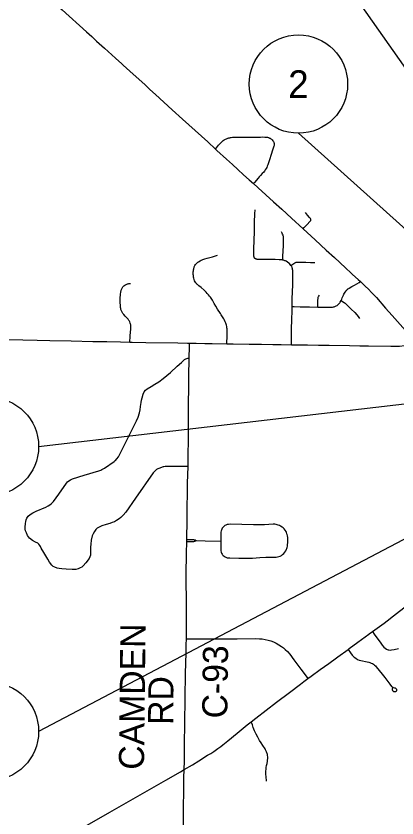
# Model space of a CAD drawing. Extents: x 1341221 to 1914484, y 79347 to 658398.
# Drawn here: x 1374791 to 1383630, y 603681 to 622283 of the extents above; entities that cross this region are included whole.
import ezdxf

# ---------------------------------------------------------------- set-up
doc = ezdxf.new("R2010")
doc.units = 0
for name, color, linetype in [('GM_X_County', 7, 'Continuous'), ('GM_X_County_Road_Text', 7, 'Continuous'), ('GM_X_Major_Lake_Text', 7, 'Continuous'), ('GM_X_State_Location', 7, 'Continuous'), ('GM_X_State_Shield', 7, 'Continuous'), ('GM_X_Township_Text', 7, 'Continuous'), ('GM_X_Unincorporated', 7, 'Continuous'), ('GM_X_US_Shield', 7, 'Continuous')]:
    doc.layers.add(name, color=color, linetype=linetype)

msp = doc.modelspace()

# ---------------------------------------------------------------- linework, layer by layer
at = {"layer": 'GM_X_County'}
for p, q in [((1382167, 623424), (1387231, 616228)), ((1381344, 619564), (1386235, 615180))]:
    msp.add_line(p, q, dxfattribs=at)
for centre in [(1381344, 620705), (1374174, 612298), (1374174, 605688)]:
    msp.add_circle(centre, 1141, dxfattribs=at)
at = {"layer": 'GM_X_County_Road_Text'}
for p, q in [((1375315, 612298), (1387479, 613715)), ((1387479, 612081), (1375315, 605688))]:
    msp.add_line(p, q, dxfattribs=at)
at = {"layer": 'GM_X_State_Location'}
msp.add_line((1378605, 604754), (1378695, 604806), dxfattribs=at)
for points in [[(1374346, 614781), (1374947, 614768), (1375280, 614764), (1375574, 614758), (1376073, 614747), (1376572, 614736), (1376898, 614730), (1377218, 614722), (1377435, 614716), (1377486, 614715), (1377806, 614710), (1378547, 614699), (1378771, 614697), (1378817, 614696), (1378969, 614693), (1379168, 614688), (1379341, 614687), (1379684, 614682), (1379833, 614679), (1380204, 614674), (1380485, 614670), (1380752, 614663), (1380944, 614662), (1381180, 614659), (1381289, 614658), (1381430, 614657), (1381551, 614654)], [(1381551, 614654), (1381813, 614650), (1382055, 614646), (1382528, 614638), (1382771, 614634), (1382968, 614630), (1383488, 614621), (1383577, 614621), (1383686, 614627), (1383808, 614638), (1383833, 614641), (1383998, 614665), (1384099, 614683), (1384167, 614697)], [(1383473, 608310), (1383481, 608316), (1383691, 608481), (1383818, 608577), (1383892, 608636), (1383985, 608720), (1384113, 608833), (1384175, 608887), (1384262, 608963)], [(1382977, 607942), (1382985, 607948), (1383059, 608003), (1383332, 608203), (1383473, 608310)], [(1382224, 607394), (1382257, 607418), (1382495, 607591), (1382520, 607609), (1382719, 607757), (1382977, 607942)], [(1381472, 606847), (1381563, 606916), (1381639, 606973), (1381851, 607127), (1382050, 607267), (1382224, 607394)], [(1378695, 604806), (1378883, 604916), (1379030, 605006), (1379237, 605134), (1379308, 605178), (1379377, 605225), (1379477, 605294), (1379542, 605340), (1379590, 605379), (1379705, 605471), (1379923, 605648), (1380156, 605838), (1380248, 605912), (1380356, 605998), (1380836, 606370), (1381133, 606593), (1381390, 606784), (1381472, 606847)], [(1369197, 599284), (1369239, 599316), (1369336, 599389), (1369617, 599601), (1369739, 599687), (1369792, 599722), (1369899, 599790), (1370152, 599941), (1371027, 600446), (1371722, 600842), (1372205, 601120), (1372852, 601483), (1373372, 601772), (1375078, 602744), (1375736, 603114), (1375804, 603153), (1376176, 603363), (1376498, 603548), (1376965, 603813), (1377238, 603969), (1378266, 604560), (1378605, 604754)]]:
    msp.add_lwpolyline(points, dxfattribs=at)
at = {"layer": 'GM_X_State_Shield'}
for points in [[(1379419, 619197), (1379444, 619226), (1379492, 619284), (1379551, 619346), (1379568, 619364), (1379582, 619378), (1379600, 619393), (1379624, 619410), (1379637, 619417), (1379649, 619424), (1379674, 619435), (1379689, 619442), (1379704, 619448), (1379716, 619452), (1379729, 619456), (1379749, 619460), (1379770, 619465), (1379786, 619467), (1379814, 619470), (1379847, 619471), (1379875, 619472), (1379924, 619472), (1379975, 619471), (1380066, 619472), (1380172, 619473), (1380310, 619475), (1380409, 619476), (1380463, 619476), (1380521, 619477), (1380567, 619476), (1380598, 619474), (1380612, 619472), (1380624, 619470), (1380639, 619466), (1380651, 619462), (1380662, 619458), (1380674, 619453), (1380685, 619447), (1380695, 619441), (1380706, 619434), (1380717, 619426), (1380725, 619418), (1380735, 619408), (1380751, 619388), (1380757, 619379), (1380762, 619371), (1380769, 619358), (1380774, 619344), (1380778, 619332), (1380779, 619322), (1380780, 619311), (1380780, 619301), (1380779, 619290), (1380777, 619278), (1380772, 619262), (1380767, 619244), (1380752, 619198), (1380736, 619148), (1380718, 619093), (1380702, 619045), (1380678, 618973), (1380654, 618898), (1380632, 618831), (1380621, 618800), (1380609, 618772), (1380596, 618748), (1380574, 618713), (1380556, 618687), (1380537, 618663), (1380505, 618627), (1380465, 618582), (1380436, 618551), (1380406, 618520), (1380323, 618424), (1380298, 618395)], [(1381180, 614659), (1381180, 614725), (1381182, 614868), (1381185, 615034), (1381186, 615089), (1381189, 615175), (1381198, 615516), (1381199, 615543), (1381202, 615721), (1381210, 616047), (1381215, 616283), (1381215, 616318), (1381213, 616352), (1381212, 616378), (1381208, 616403), (1381205, 616421), (1381200, 616439), (1381195, 616454), (1381189, 616468), (1381181, 616482), (1381171, 616497), (1381150, 616522), (1381134, 616539), (1381119, 616553), (1381089, 616576), (1381057, 616595), (1381043, 616602), (1381029, 616608), (1381000, 616617), (1380978, 616622), (1380964, 616625), (1380944, 616627), (1380921, 616630), (1380894, 616631), (1380805, 616634), (1380562, 616638), (1380415, 616638), (1380395, 616638), (1380384, 616639), (1380375, 616641), (1380365, 616643), (1380354, 616647), (1380345, 616651), (1380336, 616656), (1380330, 616662), (1380325, 616667), (1380321, 616673), (1380318, 616680), (1380315, 616687), (1380313, 616694), (1380311, 616704), (1380310, 616721), (1380312, 616903), (1380315, 617049), (1380322, 617305), (1380328, 617502), (1380334, 617694), (1380337, 617787)], [(1381450, 617347), (1381479, 617378), (1381543, 617447), (1381612, 617519), (1381626, 617533), (1381631, 617540), (1381634, 617545), (1381635, 617552), (1381635, 617558), (1381634, 617564), (1381632, 617569), (1381630, 617575), (1381627, 617579), (1381624, 617584), (1381604, 617607), (1381553, 617666), (1381506, 617725)], [(1380978, 616622), (1380985, 616705), (1380995, 616961), (1380997, 617064), (1380997, 617118), (1380996, 617146), (1380994, 617165), (1380991, 617185), (1380986, 617203), (1380977, 617224), (1380967, 617243), (1380951, 617274)], [(1379684, 614682), (1379685, 614715), (1379689, 614830), (1379691, 614929), (1379691, 614963), (1379690, 614995), (1379689, 615024), (1379685, 615053), (1379680, 615081), (1379674, 615110), (1379666, 615138), (1379658, 615161), (1379647, 615190), (1379630, 615226), (1379612, 615258), (1379598, 615283), (1379583, 615308), (1379554, 615350), (1379533, 615381), (1379464, 615485), (1379424, 615554), (1379388, 615618), (1379347, 615690), (1379304, 615759), (1379282, 615788), (1379257, 615818), (1379228, 615849), (1379204, 615875), (1379155, 615924), (1379087, 615982), (1379034, 616025), (1379005, 616052), (1378989, 616066), (1378977, 616080), (1378962, 616097), (1378948, 616119), (1378935, 616144), (1378923, 616175), (1378913, 616205), (1378909, 616225), (1378907, 616243), (1378905, 616264), (1378904, 616288), (1378904, 616346), (1378906, 616372), (1378909, 616397), (1378913, 616416), (1378916, 616434), (1378921, 616449), (1378927, 616464), (1378934, 616479), (1378941, 616493), (1378959, 616520), (1378975, 616539), (1378993, 616557), (1379008, 616570), (1379023, 616581), (1379061, 616605), (1379089, 616621), (1379106, 616628), (1379128, 616637), (1379168, 616650), (1379225, 616666), (1379346, 616698), (1379464, 616733)], [(1381171, 616497), (1381213, 616525), (1381260, 616556), (1381273, 616564), (1381289, 616570), (1381301, 616572), (1381314, 616574), (1381344, 616575), (1381398, 616574), (1381519, 616570), (1381624, 616568), (1381725, 616566)], [(1381199, 615543), (1381247, 615542), (1381384, 615540), (1381463, 615539), (1381604, 615536), (1381791, 615532), (1381852, 615531), (1381954, 615529), (1382063, 615528), (1382093, 615528), (1382118, 615529), (1382138, 615531), (1382154, 615534), (1382170, 615537), (1382187, 615543), (1382204, 615550), (1382223, 615560), (1382242, 615571), (1382256, 615581), (1382269, 615592), (1382283, 615605), (1382296, 615620), (1382305, 615631), (1382315, 615645), (1382336, 615685), (1382349, 615714), (1382361, 615743), (1382374, 615775), (1382386, 615804), (1382398, 615829), (1382412, 615855), (1382426, 615877), (1382448, 615908), (1382457, 615919), (1382467, 615931), (1382479, 615942), (1382493, 615954), (1382510, 615966), (1382521, 615974), (1382579, 616006), (1382647, 616043), (1382752, 616103), (1382783, 616121)], [(1377435, 614716), (1377435, 614740), (1377436, 614830), (1377438, 614867), (1377452, 615025), (1377454, 615054), (1377455, 615077), (1377454, 615098), (1377451, 615119), (1377446, 615138), (1377440, 615162), (1377432, 615187), (1377422, 615207), (1377411, 615224), (1377402, 615234), (1377389, 615251), (1377375, 615265), (1377324, 615321), (1377292, 615357), (1377271, 615384), (1377253, 615412), (1377239, 615442), (1377232, 615458), (1377226, 615477), (1377221, 615499), (1377218, 615523), (1377214, 615564), (1377209, 615648), (1377208, 615693), (1377210, 615748), (1377214, 615817), (1377215, 615842), (1377219, 615870), (1377223, 615890), (1377227, 615907), (1377233, 615925), (1377240, 615943), (1377254, 615972), (1377263, 615985), (1377272, 615998), (1377294, 616021), (1377319, 616041), (1377331, 616049), (1377347, 616057), (1377377, 616069), (1377395, 616073), (1377408, 616076), (1377446, 616080)], [(1381791, 615532), (1381792, 615568), (1381794, 615633), (1381797, 615688), (1381800, 615731), (1381801, 615744), (1381805, 615759), (1381811, 615774), (1381818, 615788), (1381831, 615809)], [(1382336, 615685), (1382360, 615668), (1382410, 615633), (1382428, 615620), (1382447, 615604), (1382476, 615576), (1382571, 615483), (1382650, 615404), (1382696, 615354), (1382727, 615315), (1382761, 615270)], [(1378969, 610117), (1379182, 610109), (1379540, 610104), (1379540, 610002), (1379541, 609914), (1379544, 609878), (1379551, 609847), (1379559, 609822), (1379571, 609801), (1379584, 609784), (1379599, 609767), (1379620, 609750), (1379644, 609736), (1379671, 609723), (1379693, 609718), (1379717, 609714), (1379752, 609712), (1379962, 609707), (1380160, 609706), (1380275, 609710), (1380447, 609722), (1380587, 609728), (1380708, 609727), (1380795, 609728), (1380826, 609730), (1380857, 609735), (1380886, 609743), (1380917, 609754), (1380947, 609771), (1380977, 609790), (1381003, 609816), (1381027, 609845), (1381049, 609876), (1381067, 609912), (1381075, 609931), (1381082, 609952), (1381088, 609987), (1381093, 610021), (1381097, 610062), (1381099, 610095), (1381098, 610138), (1381094, 610190), (1381089, 610226), (1381083, 610254), (1381078, 610272), (1381068, 610300), (1381056, 610323), (1381037, 610355), (1381014, 610384), (1380989, 610408), (1380963, 610429), (1380929, 610449), (1380901, 610463), (1380875, 610475), (1380853, 610482), (1380827, 610488), (1380794, 610492), (1380757, 610492), (1380559, 610482), (1380303, 610480), (1379759, 610493), (1379722, 610490), (1379693, 610486), (1379673, 610480), (1379657, 610472), (1379639, 610461), (1379622, 610450), (1379605, 610437), (1379591, 610421), (1379576, 610401), (1379564, 610379), (1379556, 610358), (1379550, 610338), (1379546, 610311), (1379541, 610192), (1379540, 610104)], [(1378752, 610143), (1378892, 610138), (1378909, 610137), (1378923, 610135), (1378934, 610133), (1378946, 610130), (1378959, 610125), (1378969, 610117)], [(1378752, 610093), (1378804, 610094), (1378893, 610095), (1378915, 610096), (1378930, 610098), (1378944, 610103), (1378955, 610109), (1378969, 610117)], [(1383059, 608003), (1383100, 607945), (1383160, 607862), (1383237, 607760), (1383290, 607689), (1383327, 607646), (1383354, 607621), (1383385, 607599), (1383406, 607588), (1383424, 607581), (1383441, 607577), (1383470, 607574), (1383507, 607577), (1383563, 607588), (1383663, 607608)], [(1378743, 607839), (1378951, 607837), (1379188, 607836), (1379514, 607835), (1379706, 607836), (1379924, 607837), (1380353, 607841), (1380442, 607839), (1380505, 607833), (1380568, 607823), (1380642, 607806), (1380703, 607788), (1380762, 607765), (1380825, 607735), (1380891, 607699), (1380950, 607661), (1380996, 607627), (1381038, 607589), (1381087, 607540), (1381141, 607477), (1381240, 607351), (1381400, 607136), (1381499, 607002), (1381563, 606916)], [(1382495, 607591), (1382554, 607512), (1382593, 607459), (1382615, 607432), (1382638, 607411), (1382673, 607385), (1382716, 607360), (1382756, 607342), (1382792, 607331), (1382942, 607302), (1382979, 607292), (1382998, 607286), (1383030, 607274), (1383059, 607261), (1383083, 607246), (1383109, 607228), (1383130, 607207), (1383147, 607189), (1383283, 607018), (1383345, 606937), (1383468, 606782), (1383507, 606731), (1383517, 606722), (1383526, 606715), (1383534, 606711), (1383541, 606708), (1383573, 606700), (1383585, 606696), (1383593, 606692), (1383605, 606683), (1383612, 606674), (1383618, 606666), (1383622, 606658), (1383623, 606650), (1383623, 606641), (1383621, 606633), (1383618, 606626), (1383613, 606619), (1383607, 606613), (1383601, 606608), (1383593, 606605), (1383585, 606603), (1383577, 606603), (1383569, 606604), (1383561, 606606), (1383554, 606610), (1383548, 606614), (1383541, 606621), (1383536, 606628), (1383533, 606635), (1383529, 606644), (1383528, 606654), (1383527, 606663), (1383529, 606676), (1383533, 606706)]]:
    msp.add_lwpolyline(points, dxfattribs=at)
at = {"layer": 'GM_X_Township_Text'}
for points in [[(1378678, 603955), (1378685, 604282), (1378685, 604492), (1378686, 604657), (1378688, 604691), (1378689, 604730), (1378695, 604806)], [(1378657, 598745), (1378656, 598778), (1378658, 599145), (1378659, 600047), (1378658, 600341), (1378663, 600917), (1378665, 601153), (1378667, 601518), (1378671, 601934), (1378671, 602151), (1378674, 602407), (1378673, 602605), (1378673, 602784), (1378674, 603085), (1378675, 603411), (1378677, 603782), (1378678, 603955)]]:
    msp.add_lwpolyline(points, dxfattribs=at)
at = {"layer": 'GM_X_Unincorporated'}
msp.add_line((1376608, 621750), (1376661, 621703), dxfattribs=at)
for points in [[(1375272, 622961), (1375606, 622657), (1375860, 622427), (1376428, 621913), (1376547, 621807), (1376608, 621750)], [(1376661, 621703), (1376842, 621540), (1377099, 621306), (1377244, 621174), (1377279, 621140)], [(1377279, 621140), (1377509, 620932), (1377776, 620691), (1377898, 620581), (1378025, 620466), (1378417, 620105), (1378657, 619889), (1378801, 619757), (1379238, 619362), (1379419, 619197), (1379453, 619166), (1379677, 618961), (1379814, 618836), (1379936, 618723), (1380069, 618603), (1380201, 618482), (1380298, 618395), (1380406, 618298), (1380764, 617972), (1380956, 617800), (1381181, 617591), (1381450, 617347), (1381735, 617088), (1381990, 616853), (1382179, 616680), (1382439, 616440), (1382569, 616319), (1382599, 616291)], [(1382599, 616291), (1382727, 616173), (1382783, 616121), (1382892, 616020), (1382971, 615945), (1383042, 615872), (1383092, 615818), (1383152, 615752), (1383367, 615509), (1383520, 615336), (1383828, 614991), (1383944, 614865), (1384005, 614800), (1384017, 614789), (1384031, 614777), (1384043, 614766), (1384064, 614749), (1384084, 614736), (1384106, 614724), (1384130, 614712), (1384167, 614697)]]:
    msp.add_lwpolyline(points, dxfattribs=at)
at = {"layer": 'GM_X_US_Shield'}
for points in [[(1378740, 609331), (1378746, 609813), (1378752, 610093), (1378752, 610126), (1378752, 610143), (1378759, 610599), (1378765, 610893), (1378769, 611213), (1378772, 611443), (1378783, 611833), (1378787, 612147), (1378791, 612396), (1378792, 612818), (1378795, 613087), (1378796, 613368), (1378798, 613592), (1378800, 613968), (1378808, 614300), (1378809, 614347), (1378816, 614614), (1378817, 614696)], [(1378783, 611833), (1378685, 611832), (1378531, 611830), (1378422, 611830), (1378255, 611830), (1378223, 611827), (1378203, 611823), (1378180, 611815), (1378125, 611793), (1378082, 611776), (1378052, 611762), (1378029, 611743), (1378000, 611718), (1377973, 611687), (1377564, 611101), (1377338, 610777), (1377277, 610701), (1377226, 610649), (1377184, 610617), (1377120, 610578), (1377073, 610550), (1377025, 610531), (1376968, 610514), (1376881, 610489), (1376782, 610458), (1376717, 610428), (1376675, 610400), (1376644, 610372), (1376610, 610324), (1376581, 610271), (1376561, 610224), (1376535, 610127), (1376525, 610034), (1376521, 609961), (1376522, 609879), (1376520, 609826), (1376516, 609777), (1376506, 609741), (1376485, 609701), (1376408, 609602), (1376347, 609533), (1376314, 609502), (1376281, 609480), (1376231, 609458), (1376178, 609448), (1376090, 609442), (1375955, 609450), (1375857, 609458), (1375794, 609468), (1375744, 609478), (1375694, 609495), (1375655, 609516), (1375624, 609545), (1375568, 609617), (1375525, 609680), (1375434, 609835), (1375377, 609938), (1375359, 609977), (1375342, 610004), (1375318, 610031), (1375293, 610053), (1375245, 610081), (1375175, 610120), (1375105, 610174), (1375059, 610234), (1375030, 610295), (1375013, 610341), (1375005, 610377), (1374999, 610428), (1375007, 610510), (1375016, 610560), (1375028, 610595), (1375044, 610634), (1375075, 610678), (1375119, 610717), (1375180, 610759), (1375261, 610798), (1375485, 610892), (1375539, 610920), (1375573, 610941), (1375606, 610971), (1375660, 611023), (1375784, 611193), (1375961, 611446), (1375986, 611476), (1376014, 611498), (1376058, 611525), (1376098, 611544), (1376372, 611630), (1376712, 611735), (1376755, 611750), (1376783, 611762), (1376815, 611777), (1376844, 611792), (1377071, 611951), (1377087, 611964), (1377099, 611974), (1377131, 612012), (1377166, 612059), (1377194, 612107), (1377433, 612583), (1377589, 612891), (1377624, 612976), (1377657, 613078), (1377671, 613147), (1377682, 613228), (1377695, 613315), (1377703, 613369), (1377714, 613428), (1377739, 613510), (1377765, 613563), (1377794, 613601), (1377832, 613635), (1377928, 613693), (1378015, 613743), (1378102, 613798), (1378204, 613873), (1378373, 614016), (1378532, 614159), (1378631, 614248), (1378702, 614312), (1378729, 614328), (1378754, 614337), (1378780, 614343), (1378809, 614347)], [(1378695, 604806), (1378700, 604996), (1378701, 605132), (1378703, 605394), (1378708, 605868), (1378717, 606456), (1378724, 607032), (1378737, 607512), (1378742, 607698), (1378743, 607839), (1378744, 607935), (1378746, 608107), (1378747, 608216), (1378744, 608543), (1378743, 608773), (1378740, 609138), (1378740, 609331)], [(1380600, 604538), (1380594, 604641), (1380591, 604687), (1380590, 604743), (1380590, 604773), (1380592, 604807), (1380597, 604851), (1380606, 604900), (1380616, 604945), (1380624, 605001), (1380629, 605034), (1380631, 605055), (1380633, 605080), (1380632, 605102), (1380628, 605131), (1380624, 605153), (1380617, 605175), (1380611, 605195), (1380604, 605212), (1380590, 605242), (1380581, 605259), (1380568, 605281), (1380514, 605361), (1380476, 605420), (1380444, 605474), (1380401, 605552), (1380363, 605626), (1380328, 605700), (1380297, 605776), (1380274, 605841), (1380248, 605912)]]:
    msp.add_lwpolyline(points, dxfattribs=at)

# ---------------------------------------------------------------- texts
at = {"layer": 'GM_X_County'}
msp.add_text('2', height=639, dxfattribs=at).set_placement((1381106, 620385))
at = {"layer": 'GM_X_Major_Lake_Text'}
for s, rotation, p in [('CAMDEN', 89.3651, (1377760, 604797)), ('C-93', 89.3139, (1379693, 605987)), ('RD', 89.5063, (1378438, 605838))]:
    msp.add_text(s, height=585, rotation=rotation, dxfattribs=at).set_placement(p)

doc.saveas('drawing.dxf')
